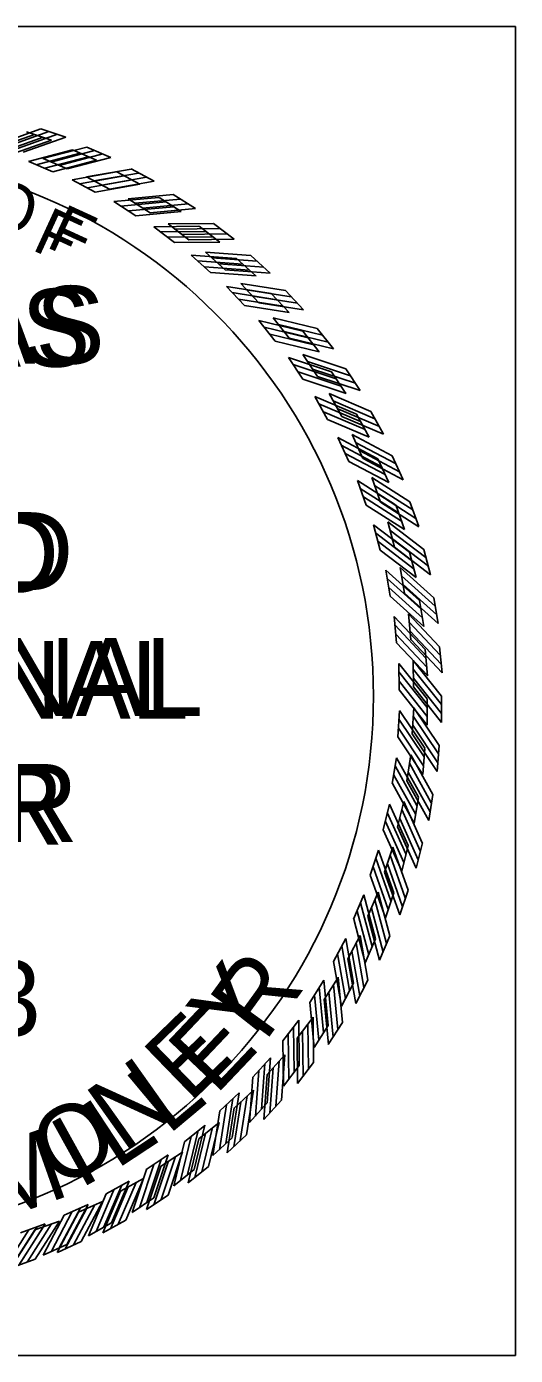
# Model space of a CAD drawing. Extents: x -2512 to 3792, y -435 to 2624.
# Drawn here: x 3189.1 to 3290.6, y 212.7 to 488.7 of the extents above; entities that cross this region are included whole.
import ezdxf

# ---------------------------------------------------------------- set-up
doc = ezdxf.new("R2010")
doc.units = 0
for name, color, linetype in [('G-ANNO-NPLT', 7, 'Continuous'), ('R_No Plot', 7, 'Continuous'), ('STAMP', 7, 'Continuous'), ('STAMP_LKM', 7, 'Continuous')]:
    doc.layers.add(name, color=color, linetype=linetype)

msp = doc.modelspace()

# ---------------------------------------------------------------- linework, layer by layer
at = {"layer": 'G-ANNO-NPLT'}
msp.add_circle((3148.72, 349.66), 112.43, dxfattribs=at)
at = {"layer": 'R_No Plot'}
msp.add_lwpolyline([(3010.37, 488.67), (3290.65, 488.67), (3290.65, 212.74), (3010.37, 212.74)], close=True, dxfattribs=at)
at = {"layer": 'STAMP'}
for p, q in [((3189.09, 466.83), (3194.25, 465.11)), ((3198.62, 463.05), (3203.62, 460.91)), ((3189.52, 460.65), (3194.53, 458.5)), ((3207.81, 458.5), (3212.62, 455.96)), ((3198.54, 456.86), (3203.36, 454.31)), ((3216.6, 453.21), (3221.18, 450.27)), ((3207.22, 452.33), (3211.81, 449.39)), ((3215.5, 447.11), (3219.83, 443.8)), ((3224.91, 447.2), (3229.24, 443.9)), ((3223.31, 441.22), (3227.36, 437.56)), ((3232.7, 440.54), (3236.74, 436.89)), ((3230.62, 434.7), (3234.35, 430.72)), ((3239.92, 433.25), (3243.64, 429.28)), ((3237.36, 427.61), (3240.75, 423.33)), ((3246.51, 425.39), (3249.89, 421.12)), ((3243.49, 419.98), (3246.51, 415.44)), ((3252.42, 417.01), (3255.44, 412.48)), ((3248.97, 411.87), (3251.61, 407.1)), ((3257.63, 408.17), (3260.26, 403.41)), ((3253.76, 403.33), (3256, 398.36)), ((3262.09, 398.94), (3264.32, 393.97)), ((3257.83, 394.43), (3259.65, 389.29)), ((3265.77, 389.36), (3267.58, 384.23)), ((3261.15, 385.23), (3262.54, 379.95)), ((3268.64, 379.52), (3270.03, 374.26)), ((3263.7, 375.78), (3264.65, 370.41)), ((3270.69, 369.47), (3271.64, 364.11)), ((3265.47, 366.15), (3265.97, 360.72)), ((3271.91, 359.29), (3272.41, 353.87)), ((3266.43, 356.41), (3266.48, 350.96)), ((3272.28, 349.04), (3272.33, 343.6)), ((3266.58, 346.62), (3266.18, 341.18)), ((3265.92, 336.86), (3265.07, 331.47)), ((3271.81, 338.79), (3271.41, 333.37)), ((3270.49, 328.62), (3269.64, 323.25)), ((3264.46, 327.18), (3263.17, 321.88)), ((3262.21, 317.65), (3260.48, 312.48)), ((3268.33, 318.6), (3267.04, 313.31)), ((3259.17, 308.35), (3257.03, 303.33)), ((3265.35, 308.78), (3263.63, 303.62)), ((3255.38, 299.33), (3252.83, 294.51)), ((3261.58, 299.25), (3259.44, 294.24)), ((3250.86, 290.65), (3247.92, 286.05)), ((3257.03, 290.05), (3254.48, 285.25)), ((3245.63, 282.37), (3242.32, 278.04)), ((3251.73, 281.27), (3248.8, 276.69)), ((3239.74, 274.55), (3236.09, 270.51)), ((3245.73, 272.96), (3242.43, 268.63)), ((3233.23, 267.25), (3229.25, 263.52)), ((3239.06, 265.16), (3235.41, 261.13)), ((3226.13, 260.51), (3221.86, 257.12)), ((3231.77, 257.95), (3227.8, 254.23)), ((3218.5, 254.38), (3213.96, 251.35)), ((3223.91, 251.36), (3219.65, 247.98)), ((3210.39, 248.9), (3205.62, 246.26)), ((3201.86, 244.11), (3196.88, 241.87)), ((3215.53, 245.44), (3211.01, 242.43)), ((3206.7, 240.24), (3201.94, 237.6)), ((3192.96, 240.03), (3187.82, 238.22)), ((3197.46, 235.78), (3192.5, 233.55))]:
    msp.add_line(p, q, dxfattribs=at)
for points in [[(3181.86, 463.11), (3190.73, 466.26)], [(3183.67, 462.55), (3192.54, 465.7)], [(3185.38, 461.96), (3194.25, 465.11)], [(3189.51, 460.65), (3198.61, 463.05)], [(3191.11, 459.94), (3200.22, 462.35)], [(3192.87, 459.24), (3201.97, 461.64)], [(3194.53, 458.51), (3203.63, 460.91)], [(3198.53, 456.86), (3207.8, 458.5)], [(3200.07, 456.02), (3209.34, 457.67)], [(3201.76, 455.18), (3211.03, 456.82)], [(3203.36, 454.31), (3212.63, 455.96)], [(3207.21, 452.33), (3216.59, 453.21)], [(3208.68, 451.38), (3218.05, 452.25)], [(3210.29, 450.39), (3219.67, 451.26)], [(3211.81, 449.4), (3221.18, 450.27)], [(3215.49, 447.11), (3224.9, 447.21)], [(3216.87, 446.03), (3226.28, 446.13)], [(3218.4, 444.92), (3227.81, 445.02)], [(3219.83, 443.81), (3229.24, 443.9)], [(3223.3, 441.22), (3232.69, 440.54)], [(3224.59, 440.03), (3233.98, 439.35)], [(3226.02, 438.8), (3235.41, 438.12)], [(3227.36, 437.57), (3236.75, 436.89)], [(3230.61, 434.7), (3239.91, 433.25)], [(3231.79, 433.42), (3241.1, 431.96)], [(3233.12, 432.07), (3242.42, 430.61)], [(3234.35, 430.73), (3243.65, 429.28)], [(3237.35, 427.61), (3246.5, 425.39)], [(3238.42, 426.23), (3247.57, 424.01)], [(3239.63, 424.77), (3248.78, 422.55)], [(3240.75, 423.34), (3249.89, 421.12)], [(3243.48, 419.98), (3252.42, 417.01)], [(3244.44, 418.51), (3253.37, 415.55)], [(3245.52, 416.96), (3254.46, 414)], [(3246.51, 415.45), (3255.45, 412.48)], [(3248.96, 411.87), (3257.62, 408.18)], [(3249.79, 410.33), (3258.45, 406.64)], [(3250.75, 408.7), (3259.41, 405)], [(3251.61, 407.1), (3260.27, 403.41)], [(3253.75, 403.34), (3262.08, 398.94)], [(3254.46, 401.73), (3262.78, 397.34)], [(3255.27, 400.03), (3263.59, 395.63)], [(3256, 398.37), (3264.32, 393.97)], [(3257.82, 394.44), (3265.76, 389.37)], [(3258.39, 392.78), (3266.33, 387.71)], [(3259.06, 391.01), (3267, 385.94)], [(3259.65, 389.3), (3267.58, 384.23)], [(3261.15, 385.23), (3268.63, 379.52)], [(3261.58, 383.53), (3269.06, 377.83)], [(3262.1, 381.72), (3269.59, 376.01)], [(3262.54, 379.96), (3270.03, 374.25)], [(3263.7, 375.78), (3270.69, 369.48)], [(3263.99, 374.06), (3270.98, 367.75)], [(3264.36, 372.2), (3271.35, 365.9)], [(3264.65, 370.41), (3271.64, 364.11)], [(3265.46, 366.16), (3271.91, 359.29)], [(3265.6, 364.41), (3272.05, 357.55)], [(3265.82, 362.53), (3272.27, 355.67)], [(3265.97, 360.73), (3272.42, 353.86)], [(3266.42, 356.42), (3272.28, 349.05)], [(3266.42, 354.66), (3272.28, 347.29)], [(3266.48, 352.77), (3272.34, 345.4)], [(3266.48, 350.96), (3272.34, 343.59)], [(3266.57, 346.63), (3271.8, 338.8)], [(3266.33, 343), (3271.56, 335.17)], [(3266.43, 344.88), (3271.66, 337.06)], [(3266.18, 341.19), (3271.41, 333.36)], [(3265.92, 336.86), (3270.48, 328.63)], [(3265.63, 335.14), (3270.19, 326.9)], [(3265.08, 331.48), (3269.64, 323.24)], [(3265.38, 333.26), (3269.94, 325.03)], [(3264.46, 327.19), (3268.33, 318.6)], [(3263.62, 323.64), (3267.49, 315.06)], [(3264.03, 325.49), (3267.9, 316.91)], [(3263.18, 321.89), (3267.05, 313.3)], [(3262.2, 317.66), (3265.35, 308.79)], [(3261.64, 316.01), (3264.78, 307.13)], [(3260.49, 312.49), (3263.64, 303.61)], [(3261.08, 314.2), (3264.23, 305.33)], [(3258.47, 306.75), (3260.87, 297.65)], [(3259.17, 308.36), (3261.58, 299.25)], [(3257.76, 305), (3260.17, 295.9)], [(3257.04, 303.34), (3259.44, 294.24)], [(3255.38, 299.33), (3257.03, 290.06)], [(3253.7, 296.1), (3255.34, 286.83)], [(3254.55, 297.79), (3256.19, 288.52)], [(3252.84, 294.51), (3254.48, 285.24)], [(3250.86, 290.65), (3251.73, 281.28)], [(3248.92, 287.57), (3249.79, 278.2)], [(3249.9, 289.19), (3250.77, 279.81)], [(3247.93, 286.06), (3248.8, 276.68)], [(3245.63, 282.38), (3245.73, 272.96)], [(3243.44, 279.47), (3243.54, 270.06)], [(3244.56, 281), (3244.65, 271.58)], [(3242.33, 278.04), (3242.43, 268.62)], [(3238.56, 273.27), (3237.88, 263.88)], [(3239.74, 274.56), (3239.06, 265.17)], [(3236.09, 270.51), (3235.41, 261.12)], [(3237.32, 271.84), (3236.64, 262.45)], [(3231.94, 266.07), (3230.49, 256.77)], [(3233.23, 267.26), (3231.77, 257.96)], [(3229.26, 263.52), (3227.8, 254.22)], [(3230.59, 264.75), (3229.14, 255.45)], [(3224.75, 259.44), (3222.53, 250.29)], [(3226.13, 260.52), (3223.91, 251.37)], [(3221.87, 257.12), (3219.65, 247.97)], [(3223.3, 258.23), (3221.08, 249.09)], [(3218.5, 254.39), (3215.54, 245.45)], [(3213.97, 251.35), (3211.01, 242.42)], [(3215.49, 252.35), (3212.52, 243.41)], [(3217.04, 253.43), (3214.07, 244.49)], [(3210.4, 248.91), (3206.7, 240.25)], [(3205.63, 246.26), (3201.93, 237.6)], [(3207.22, 247.12), (3203.53, 238.46)], [(3208.86, 248.07), (3205.16, 239.41)], [(3200.26, 243.41), (3195.86, 235.08)], [(3201.86, 244.11), (3197.47, 235.79)], [(3196.89, 241.87), (3192.5, 233.54)], [(3198.55, 242.6), (3194.16, 234.27)], [(3189.54, 238.8), (3184.47, 230.87)], [(3191.31, 239.47), (3186.24, 231.54)], [(3192.96, 240.04), (3187.89, 232.11)]]:
    msp.add_lwpolyline(points, dxfattribs=at)
at = {"layer": 'STAMP_LKM'}
for p, q in [((3192.06, 467.42), (3197.23, 465.7)), ((3201.6, 463.65), (3206.6, 461.51)), ((3192.5, 461.24), (3197.51, 459.1)), ((3210.79, 459.1), (3215.6, 456.55)), ((3201.52, 457.45), (3206.34, 454.9)), ((3210.2, 452.93), (3214.79, 449.99)), ((3219.57, 453.8), (3224.15, 450.87)), ((3218.47, 447.7), (3222.81, 444.39)), ((3227.89, 447.8), (3232.21, 444.5)), ((3226.29, 441.81), (3230.34, 438.16)), ((3235.68, 441.13), (3239.72, 437.48)), ((3233.59, 435.3), (3237.32, 431.32)), ((3242.9, 433.84), (3246.62, 429.87)), ((3240.33, 428.2), (3243.72, 423.93)), ((3249.48, 425.98), (3252.87, 421.72)), ((3246.47, 420.57), (3249.49, 416.03)), ((3255.4, 417.6), (3258.42, 413.08)), ((3251.95, 412.46), (3254.59, 407.69)), ((3260.61, 408.77), (3263.24, 404.01)), ((3256.74, 403.93), (3258.97, 398.95)), ((3265.06, 399.53), (3267.29, 394.57)), ((3260.81, 395.03), (3262.63, 389.89)), ((3268.74, 389.96), (3270.56, 384.83)), ((3264.13, 385.82), (3265.52, 380.55)), ((3271.62, 380.11), (3273, 374.85)), ((3266.68, 376.37), (3267.63, 371)), ((3273.67, 370.06), (3274.62, 364.71)), ((3268.44, 366.74), (3268.94, 361.31)), ((3274.89, 359.88), (3275.39, 354.46)), ((3269.4, 357), (3269.45, 351.55)), ((3275.26, 349.63), (3275.31, 344.19)), ((3269.56, 347.22), (3269.16, 341.78)), ((3268.9, 337.45), (3268.05, 332.06)), ((3274.78, 339.39), (3274.39, 333.96)), ((3273.46, 329.22), (3272.62, 323.84)), ((3267.44, 327.77), (3266.15, 322.47)), ((3265.18, 318.25), (3263.46, 313.08)), ((3271.31, 319.19), (3270.02, 313.9)), ((3268.33, 309.38), (3266.61, 304.21)), ((3262.15, 308.94), (3260.01, 303.93)), ((3258.36, 299.92), (3255.81, 295.1)), ((3264.55, 299.84), (3262.42, 294.84)), ((3253.84, 291.24), (3250.9, 286.65)), ((3260, 290.65), (3257.46, 285.84)), ((3248.61, 282.96), (3245.3, 278.63)), ((3254.71, 281.87), (3251.77, 277.28)), ((3242.72, 275.15), (3239.06, 271.1)), ((3248.71, 273.55), (3245.4, 269.23)), ((3236.21, 267.84), (3232.23, 264.11)), ((3242.04, 265.76), (3238.39, 261.72)), ((3229.11, 261.1), (3224.84, 257.72)), ((3234.75, 258.54), (3230.78, 254.82)), ((3221.48, 254.97), (3216.94, 251.95)), ((3226.89, 251.95), (3222.63, 248.57)), ((3213.37, 249.49), (3208.6, 246.85)), ((3218.51, 246.04), (3213.99, 243.02)), ((3204.84, 244.7), (3199.86, 242.46)), ((3195.94, 240.63), (3190.79, 238.81)), ((3209.68, 240.83), (3204.91, 238.2)), ((3200.44, 236.38), (3195.48, 234.14)), ((3190.87, 232.7), (3185.74, 230.88))]:
    msp.add_line(p, q, dxfattribs=at)
for points in [[(3183.18, 464.27), (3192.05, 467.42)], [(3184.84, 463.71), (3193.71, 466.85)], [(3186.64, 463.15), (3195.52, 466.3)], [(3188.36, 462.56), (3197.23, 465.71)], [(3192.49, 461.24), (3201.59, 463.65)], [(3194.09, 460.54), (3203.19, 462.94)], [(3195.85, 459.83), (3204.95, 462.24)], [(3197.5, 459.11), (3206.61, 461.51)], [(3201.51, 457.45), (3210.78, 459.09)], [(3203.05, 456.62), (3212.32, 458.26)], [(3204.74, 455.77), (3214.01, 457.41)], [(3206.33, 454.91), (3215.6, 456.55)], [(3210.19, 452.93), (3219.56, 453.8)], [(3211.66, 451.97), (3221.03, 452.84)], [(3213.27, 450.99), (3222.64, 451.86)], [(3214.79, 449.99), (3224.16, 450.87)], [(3218.47, 447.7), (3227.88, 447.8)], [(3219.85, 446.63), (3229.26, 446.72)], [(3221.38, 445.51), (3230.79, 445.61)], [(3222.81, 444.4), (3232.22, 444.5)], [(3226.28, 441.81), (3235.67, 441.13)], [(3227.57, 440.63), (3236.96, 439.95)], [(3229, 439.39), (3238.39, 438.71)], [(3230.33, 438.16), (3239.72, 437.48)], [(3233.59, 435.3), (3242.89, 433.84)], [(3234.77, 434.01), (3244.07, 432.56)], [(3236.1, 432.66), (3245.4, 431.21)], [(3237.32, 431.33), (3246.62, 429.87)], [(3240.33, 428.2), (3249.48, 425.98)], [(3241.4, 426.82), (3250.55, 424.6)], [(3242.61, 425.37), (3251.76, 423.15)], [(3243.72, 423.94), (3252.87, 421.72)], [(3246.46, 420.57), (3255.39, 417.61)], [(3247.42, 419.11), (3256.35, 416.14)], [(3248.5, 417.56), (3257.43, 414.59)], [(3249.49, 416.04), (3258.42, 413.08)], [(3251.94, 412.47), (3260.6, 408.77)], [(3252.77, 410.93), (3261.43, 407.23)], [(3253.72, 409.29), (3262.38, 405.6)], [(3254.59, 407.7), (3263.25, 404)], [(3256.73, 403.93), (3265.06, 399.54)], [(3257.43, 402.33), (3265.76, 397.93)], [(3258.25, 400.62), (3266.57, 396.23)], [(3258.98, 398.96), (3267.3, 394.57)], [(3260.8, 395.03), (3268.74, 389.96)], [(3261.37, 393.38), (3269.3, 388.31)], [(3262.04, 391.61), (3269.97, 386.54)], [(3262.63, 389.89), (3270.56, 384.82)], [(3264.12, 385.83), (3271.61, 380.12)], [(3264.55, 384.13), (3272.04, 378.42)], [(3265.08, 382.31), (3272.56, 376.6)], [(3265.52, 380.55), (3273.01, 374.85)], [(3266.68, 376.38), (3273.67, 370.07)], [(3266.96, 374.65), (3273.95, 368.34)], [(3267.33, 372.8), (3274.32, 366.49)], [(3267.63, 371.01), (3274.62, 364.7)], [(3268.44, 366.75), (3274.88, 359.89)], [(3268.58, 365), (3275.03, 358.14)], [(3268.8, 363.13), (3275.24, 356.27)], [(3268.95, 361.32), (3275.39, 354.46)], [(3269.4, 357.01), (3275.26, 349.64)], [(3269.4, 355.26), (3275.26, 347.89)], [(3269.46, 353.37), (3275.31, 346)], [(3269.46, 351.56), (3275.31, 344.19)], [(3269.41, 345.48), (3274.64, 337.65)], [(3269.55, 347.22), (3274.78, 339.4)], [(3269.31, 343.59), (3274.54, 335.76)], [(3269.16, 341.78), (3274.39, 333.96)], [(3268.9, 337.46), (3273.46, 329.23)], [(3268.61, 335.73), (3273.17, 327.5)], [(3268.06, 332.07), (3272.62, 323.84)], [(3268.35, 333.86), (3272.92, 325.62)], [(3267.01, 326.08), (3270.88, 317.5)], [(3267.44, 327.78), (3271.3, 319.2)], [(3266.6, 324.24), (3270.47, 315.66)], [(3266.15, 322.48), (3270.02, 313.9)], [(3265.18, 318.26), (3268.33, 309.38)], [(3264.06, 314.79), (3267.2, 305.92)], [(3264.61, 316.6), (3267.76, 307.73)], [(3263.47, 313.08), (3266.61, 304.21)], [(3261.45, 307.35), (3263.85, 298.25)], [(3262.15, 308.95), (3264.55, 299.85)], [(3260.01, 303.93), (3262.42, 294.83)], [(3260.74, 305.59), (3263.14, 296.49)], [(3257.53, 298.39), (3259.17, 289.12)], [(3258.36, 299.93), (3260, 290.66)], [(3256.68, 296.7), (3258.32, 287.43)], [(3255.82, 295.1), (3257.46, 285.83)], [(3252.88, 289.78), (3253.75, 280.41)], [(3253.84, 291.25), (3254.71, 281.88)], [(3251.89, 288.17), (3252.77, 278.8)], [(3250.9, 286.65), (3251.78, 277.28)], [(3247.54, 281.59), (3247.63, 272.18)], [(3248.61, 282.97), (3248.71, 273.56)], [(3246.42, 280.06), (3246.52, 270.65)], [(3245.31, 278.63), (3245.4, 269.22)], [(3241.54, 273.87), (3240.85, 264.48)], [(3242.72, 275.16), (3242.04, 265.77)], [(3239.07, 271.1), (3238.39, 261.71)], [(3240.3, 272.44), (3239.62, 263.05)], [(3236.21, 267.85), (3234.75, 258.55)], [(3233.57, 265.34), (3232.11, 256.04)], [(3234.92, 266.67), (3233.46, 257.37)], [(3232.23, 264.12), (3230.78, 254.81)], [(3227.73, 260.04), (3225.51, 250.89)], [(3229.11, 261.11), (3226.89, 251.96)], [(3224.84, 257.72), (3222.63, 248.57)], [(3226.27, 258.83), (3224.06, 249.68)], [(3220.02, 254.02), (3217.05, 245.09)], [(3221.48, 254.98), (3218.52, 246.05)], [(3216.95, 251.95), (3213.98, 243.01)], [(3218.47, 252.94), (3215.5, 244.01)], [(3211.83, 248.67), (3208.14, 240.01)], [(3213.37, 249.5), (3209.68, 240.84)], [(3208.61, 246.85), (3204.91, 238.19)], [(3210.2, 247.72), (3206.51, 239.06)], [(3201.53, 243.19), (3197.13, 234.87)], [(3203.24, 244), (3198.84, 235.68)], [(3204.84, 244.71), (3200.44, 236.38)], [(3194.28, 240.07), (3189.21, 232.13)], [(3195.94, 240.64), (3190.87, 232.7)], [(3199.87, 242.46), (3195.47, 234.14)], [(3190.8, 238.81), (3185.73, 230.88)], [(3192.52, 239.4), (3187.45, 231.47)]]:
    msp.add_lwpolyline(points, dxfattribs=at)

# ---------------------------------------------------------------- texts
at = {"layer": 'STAMP'}
for s, height, rotation, p in [('F', 9.9, 335.3628, (3189.91, 442.41)), ('Y', 15.03, 51.7852, (3233.52, 275.6)), ('E', 15.03, 44.1244, (3222.89, 264.96)), ('N', 15.03, 35.3692, (3209.14, 254.66)), ('O', 15.03, 27.3436, (3195.28, 247.15))]:
    msp.add_text(s, height=height, rotation=rotation, dxfattribs=at).set_placement(p)
for s, height, p in [('ARKANSAS', 16.155, (3084.69, 418.05)), ('LICENSED', 16.155, (3087.77, 371.1)), ('PROFESSIONAL', 16.1547, (3054.69, 344.94)), ('ENGINEER', 16.155, (3083.92, 318.79))]:
    msp.add_text(s, height=height, dxfattribs=at).set_placement(p)
at = {"layer": 'STAMP_LKM'}
for s, height, rotation, p in [('O', 9.9, 341.2218, (3179.54, 448.22)), ('F', 9.9, 335.3628, (3192.88, 443.01)), ('R', 15.03, 54.15, (3238.59, 277.6)), ('E', 15.03, 46.4892, (3228.34, 266.59)), ('L', 15.03, 39.9228, (3218.44, 258.31)), ('L', 15.03, 33.3564, (3207.67, 251.22)), ('I', 15.03, 28.9788, (3200.07, 247.19)), ('M', 15.03, 19.494, (3182.68, 240.53))]:
    msp.add_text(s, height=height, rotation=rotation, dxfattribs=at).set_placement(p)
for s, height, p in [('ARKANSAS', 16.155, (3087.67, 418.65)), ('LICENSED', 16.155, (3090.75, 371.69)), ('PROFESSIONAL', 16.1547, (3057.67, 345.54)), ('ENGINEER', 16.155, (3086.9, 319.38)), ('No.18633', 15.578, (3101.67, 279.1))]:
    msp.add_text(s, height=height, dxfattribs=at).set_placement(p)

doc.saveas('drawing.dxf')
